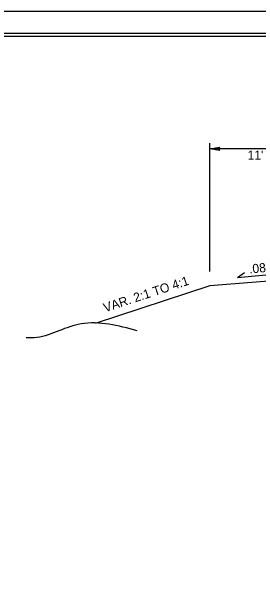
# Model space of a CAD drawing. Extents: x 2532463 to 2534146, y 189689 to 190784.
# Drawn here: x 2533037 to 2533260, y 190267 to 190784 of the extents above; entities that cross this region are included whole.
import ezdxf

# ---------------------------------------------------------------- set-up
doc = ezdxf.new("R2010")
doc.units = 0
for name, color, linetype in [('Old_Level_1', 7, 'Continuous'), ('Old_Level_10', 7, 'Continuous'), ('Old_Level_18', 7, 'Continuous'), ('Old_Level_2', 7, 'Continuous'), ('Old_Level_3', 7, 'Continuous'), ('Old_Level_42', 7, 'Continuous'), ('Old_Level_50', 7, 'Continuous'), ('Old_Level_51', 7, 'Continuous')]:
    doc.layers.add(name, color=color, linetype=linetype)

msp = doc.modelspace()

# ---------------------------------------------------------------- linework, layer by layer
at = {"layer": 'Old_Level_1'}
for p, q in [((2533294.8, 190542.66), (2533216.29, 190536.38)), ((2533216.29, 190536.38), (2533112.87, 190502.36))]:
    msp.add_line(p, q, dxfattribs=at)
at = {"layer": 'Old_Level_10'}
msp.add_spline([(2533150.76, 190495.8), (2533100.15, 190501.94), (2533080.22, 190495.8), (2533060.28, 190489.67), (2533050.67, 190489.48)], degree=3, dxfattribs=at)
at = {"layer": 'Old_Level_18'}
msp.add_lwpolyline([(2534129.31, 190761.68), (2532629.31, 190761.68), (2532629.31, 189711.68), (2534129.31, 189711.68)], close=True, dxfattribs=at)
at = {"layer": 'Old_Level_2'}
for p, q in [((2533216.29, 190549.43), (2533216.29, 190665.28)), ((2533327.27, 190660.13), (2533216.33, 190660.13)), ((2533241.37, 190543.9), (2533247.6, 190548.31)), ((2533241.37, 190543.9), (2533280.07, 190547.5))]:
    msp.add_line(p, q, dxfattribs=at)
at = {"layer": 'Old_Level_3'}
for p, q in [((2533216.33, 190660.13), (2533225.24, 190661.7)), ((2533225.24, 190658.56), (2533216.33, 190660.13)), ((2533225.24, 190661.7), (2533224.08, 190660.13)), ((2533224.08, 190660.13), (2533225.24, 190658.56))]:
    msp.add_line(p, q, dxfattribs=at)
at = {"layer": 'Old_Level_50'}
msp.add_lwpolyline([(2532475.81, 189709.18), (2534141.81, 189709.18), (2534141.81, 190764.18), (2532475.81, 190764.18)], close=True, dxfattribs=at)
at = {"layer": 'Old_Level_51'}
msp.add_lwpolyline([(2532462.81, 189689.18), (2534146.31, 189689.18), (2534146.31, 190784.18), (2532462.81, 190784.18)], close=True, dxfattribs=at)

# ---------------------------------------------------------------- texts
at = {"layer": 'Old_Level_2'}
for s, rotation, p in [("11'  W/GR", 359.9999, (2533250.46, 190650.33)), ('.08', 5.8332, (2533252.19, 190547.38))]:
    msp.add_text(s, height=8.201, rotation=rotation, dxfattribs=at).set_placement(p)
at = {"layer": 'Old_Level_42'}
msp.add_text('VAR. 2:1 TO 4:1', height=8.2009, rotation=18.2581, dxfattribs=at).set_placement((2533121.84, 190512.39))

doc.saveas('drawing.dxf')
